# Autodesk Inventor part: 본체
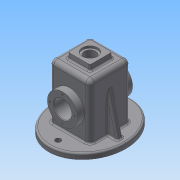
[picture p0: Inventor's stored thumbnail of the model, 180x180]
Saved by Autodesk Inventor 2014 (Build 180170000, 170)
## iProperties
Created: 2017-07
Part Number: 본체
Material: Generic
Document SubType Name: Modeling
Designer: user
Density: 1 g/cm^3
Appearance: Default
Author: user
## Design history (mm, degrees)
sketch "Sketch1"
  geometry: 1 further point
sketch "Sketch2" dims "d1" = 65, "d2" = 75
  geometry: 2 further points; 1 other entity
  constraints: 1 coincident, 2 other
extrude "Extrusion1" new body sketch "Sketch2" distance "d3" = 10; taper "d4" = 0 deg
sketch "Sketch3"
  geometry: L1 (-37, 0)-(37, 0); L2 (37, 0)-(37, 110); L3 (37, 110)-(-37, 110); L4 (-37, 110)-(-37, 0); 2 further points
  constraints: 8 end point, 2 coincident, 2 parallel, 1 horizontal, 1 midpoint, 1 perpendicular
  dimensions: "d5" = 74 distance of L2.end L3.end; "d6" = 110 distance of L1.end L2.end
extrude "Extrusion2" join sketch "Sketch3" stored distance "d7" = 74; taper "d8" = 0 deg
sketch "Sketch4"
  geometry: L1 (-37, 110)-(37, 110) reference; L2 (-37, 10)-(37, 10) reference; L3 (-37, 10)-(-37, 110) reference; L4 (-37, 110)-(37, 110) reference; L5 (37, 110)-(37, 10) reference; L6 (-32, 105)-(-32, 0); L7 (32, 0)-(32, 105); L8 (32, 105)-(-32, 105); L9 (-75, 0)-(75, 0) reference; L10 (-32, 0)-(32, 0); 1 further point
  constraints: 8 end point, 2 point on line, 1 collinear
  dimensions: "d9" = 5 distance between parallel lines of L1 L8
extrude "Extrusion3" cut sketch "Sketch4" stored distance "d10" = 64; taper "d11" = 0 deg
sketch "Sketch5"
  geometry: L1 (17, 17)-(57, 17); L2 (57, 17)-(57, 57); L3 (57, 57)-(17, 57); L4 (17, 57)-(17, 17); L5 (17, 17)-(57, 57); L6 (57, 17)-(17, 57); 1 further point
  constraints: 12 end point, 2 midpoint, 2 parallel, 1 horizontal, 1 perpendicular
  dimensions: "d12" = 40 distance of L3.end L2.end; "d13" = 40 distance of L2.end L1.end
extrude "Extrusion4" join sketch "Sketch5" distance "d14" = 10; taper "d15" = 0 deg
sketch "Sketch6"
  geometry: 2 further points
  constraints: 1 coincident
hole "Hole1" sketch "Sketch6" at (37, 37) diameter "d16" = 21; stored, may be unused: countersink angle "d20" = 90 deg, drill point angle "d22" = 118 deg; dims "d17" = 6, "d18" = 28, "d19" = 4, "d21" = 8
feature "FaceDraft1" dims angle "d23" = 5 deg
sketch "Sketch7"
  geometry: L1 (10, -65)-(10, 65) reference; L2 (10, -65)-(10, 65) reference; L3 (0, 65)-(0, -65) reference; L4 (10, 55)-(102.248, 32); L5 (10, -55)-(102.248, -32); L6 (11.934, 54.518)-(64.26, 54.518); L7 (10, -55)-(75.922, -55); L8 (105, 32)-(0, 32) reference; L9 (0, -32)-(105, -32) reference; L10 (102.248, 32)-(10, 32); L11 (10, 37)-(10, -37) reference; L12 (102.248, -32)-(10, -32); 1 further point
  constraints: 12 end point, 9 point on line, 1 parallel, 1 perpendicular
  dimensions: "d24" = 10 distance of L4.start L1.end; "d25" = 10 distance of L1.start L5.start; "d26" = 14 deg angle of L6 L4; "d27" = 14 deg angle of L7 L5
extrude "Extrusion5" join sketch "Sketch7" stored distance "d28" = 10; taper "d29" = 0 deg
sketch "Sketch8"
  geometry: L1 (-75, 0)-(75, 0) reference; L2 (-37, 10)-(-37, 110) reference; L3 (37, 110)-(37, 10) reference; L4 (-32, 105)-(32, 105) reference; L5 (-32, 0)-(-32, 105) reference; L6 (32, 0)-(-32, 0) reference; L7 (32, 105)-(32, 0) reference; L8 (25, 75.5)-(25, 55); L9 (32, 82.5)-(25, 75.5); L10 (-32, 27.5)-(32, 27.5); L11 (-32, 82.5)-(-25, 75.5); L12 (50, 82.5)-(32, 82.5); L13 (32, 82.5)-(32, 27.5); L14 (-50, 55)-(-50, 82.5); L15 (-50, 82.5)-(-32, 82.5); L16 (-25, 75.5)-(-25, 55); L17 (50, 82.5)-(50, 55); L18 (-50, 55)-(-25, 55); L19 (25, 55)-(50, 55); L20 (-25, 55)-(25, 55); L21 (-50, 55)-(-32, 55); L22 (-32, 55)-(-32, 82.5); L23 (-32, 82.5)-(-50, 82.5); L24 (-50, 82.5)-(-50, 55); L25 (32, 55)-(50, 55); L26 (50, 55)-(50, 82.5); L27 (50, 82.5)-(32, 82.5); L28 (32, 82.5)-(32, 55); L29 (-32, 82.5)-(-25, 75.5); L30 (-25, 55)-(-32, 55); L31 (25, 55)-(25, 75.5); L32 (32, 82.5)-(32, 55); L33 (32, 105)-(32, 0) reference; L34 (32, 82.5)-(25, 75.5); L35 (25, 55)-(32, 55); 5 further points
  constraints: 54 end point, 7 collinear, 6 parallel, 4 perpendicular, 3 point on line, 2 coincident, 2 horizontal, 2 horizontal alignment, 1 midpoint
  dimensions: "d41" = 18 distance of L12.end L12.start; "d42" = 18 distance of L14.end L15.end; "d46" = 55 distance between parallel lines of L1 L20
revolve "Revolution1" sketch "Sketch8" stored, may be unused: angle "d47" = 90 deg
sketch "Sketch9"
  geometry: C1 r 27.5 at (0, 0) reference; C2 r 16 at (0, 0); 1 further point
  constraints: 1 centre point, 1 coincident
  dimensions: "d48" = 32 diameter of C2
extrude "Extrusion6" cut sketch "Sketch9" distance "d49" = 100; taper "d50" = 0 deg
sketch "Sketch10"
  geometry: C1 r 27.5 at (0, 0) reference; A1 r 22.5 centre (0, 0) between (0, 22.5) and (-22.5, 0); 3 further points
  constraints: 4 point on circle, 1 centre point, 1 coincident
  dimensions: "d51" = 45 diameter of A1
hole "Hole2" sketch "Sketch10" at (0, 22.5), (-22.5, 0), (0, -22.5), (22.5, 0) diameter "d52" = 3.242; stored, may be unused: countersink angle "d56" = 90 deg, drill point angle "d58" = 118 deg; dims "d53" = 8, "d54" = 28, "d55" = 4, "d57" = 10
mirror "Mirror1"
sketch "Sketch11"
  geometry: L1 (58, -19.058)-(-58, -19.058); L2 (-58, -19.058)-(-58, 19.058); L3 (-58, 19.058)-(58, 19.058); L4 (58, 19.058)-(58, -19.058); L5 (58, -19.058)-(-58, 19.058); L6 (-58, -19.058)-(58, 19.058); 3 further points; 1 other entity
  constraints: 12 end point, 4 midpoint, 2 parallel, 1 horizontal, 1 perpendicular, 1 other
  dimensions: "d59" = 116 distance of L2.end L3.end
hole "Hole3" sketch "Sketch11" at (-58, 0), (58, 0) diameter "d60" = 10; stored, may be unused: countersink angle "d64" = 90 deg, drill point angle "d66" = 118 deg; dims "d61" = 8, "d62" = 28, "d63" = 4, "d65" = 10
chamfer "Chamfer1" distance "d67" = 1; stored, may be unused: second distance "d68" = 2, angle "d69" = 45 deg
fillet "Fillet1" dims "d70" = 8
fillet "Fillet2" dims "d71" = 3
fillet "Fillet3" dims "d72" = 3
fillet "Fillet4" dims "d73" = 3
fillet "Fillet5" dims "d74" = 3
fillet "Fillet6" dims "d75" = 0.5
fillet "Fillet7" dims "d76" = 3
fillet "Fillet8" dims "d77" = 3
fillet "Fillet9" dims "d78" = 3
fillet "Fillet10" dims "d79" = 3
fillet "Fillet11" dims "d80" = 3
workplane "Work Plane1"
sketch "Sketch14"
  geometry: L1 (120, 17.011)-(120, -17.011) reference; L2 (13, -37)-(102, -37) reference; 2 further points
  constraints: 1 other
  dimensions: "d90" = 30 distance from line of L1 point (90, 0); "d91" = 37 distance from line of L2 point (90, 0)
emboss "Emboss3" sketch "Sketch14" dims "d1" = 65, "d2" = 75, "d9" = 5, "d92" = 0.5, "d93" = 0
fillet "Fillet12" dims "d94" = 0.5
fillet "Fillet13" dims "d95" = 3
body "Solid1"
node "Projected Loop1"
node "Projected Loop2"
node "Projected Loop3"
other parameters: "d31" = 7
